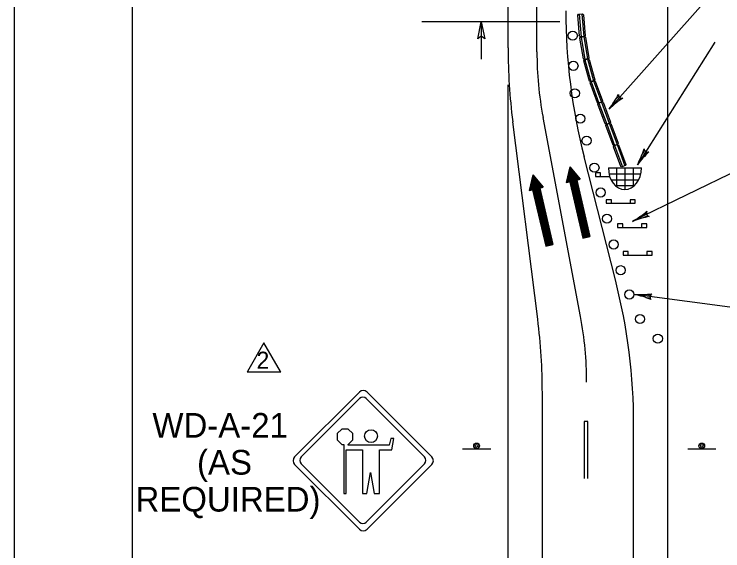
# Model space of a CAD drawing. Extents: x 2171 to 2395, y 134 to 413.
# Drawn here: x 2178.7 to 2238.8, y 274.1 to 319.6 of the extents above; entities that cross this region are included whole.
import ezdxf

# ---------------------------------------------------------------- set-up
doc = ezdxf.new("R2010")
doc.units = 0
for name, color, linetype in [('Level 1', 7, 'Continuous'), ('Level 10', 7, 'Continuous'), ('Level 12', 7, 'Continuous'), ('Level 2', 7, 'Continuous'), ('Level 20', 7, 'Continuous'), ('Level 4', 7, 'Continuous'), ('Level 44', 7, 'Continuous'), ('Level 5', 7, 'Continuous'), ('Level 60', 7, 'Continuous')]:
    doc.layers.add(name, color=color, linetype=linetype)

msp = doc.modelspace()

# ---------------------------------------------------------------- linework, layer by layer
at = {"layer": 'Level 1'}
for p, q in [((2206.522, 284.454), (2206.138, 284.07)), ((2207.064, 284.454), (2206.522, 284.454)), ((2207.448, 284.07), (2207.064, 284.454)), ((2206.138, 284.07), (2206.138, 283.528)), ((2207.448, 283.528), (2207.448, 284.07)), ((2210.68, 283.657), (2210.541, 283.074)), ((2210.924, 283.657), (2210.68, 283.657)), ((2210.765, 282.683), (2210.924, 283.657)), ((2206.138, 283.528), (2206.522, 283.144)), ((2206.522, 283.144), (2206.696, 283.144)), ((2206.696, 283.144), (2206.696, 278.991)), ((2207.064, 283.144), (2207.448, 283.528)), ((2207.064, 283.074), (2207.064, 283.144)), ((2210.541, 283.074), (2207.064, 283.074)), ((2206.886, 278.991), (2206.886, 282.683)), ((2206.886, 282.683), (2208.268, 282.683)), ((2208.268, 282.683), (2208.268, 278.991)), ((2209.718, 278.991), (2209.718, 282.683)), ((2209.718, 282.683), (2210.765, 282.683)), ((2208.635, 278.991), (2208.963, 280.76)), ((2208.963, 280.76), (2209.271, 278.991)), ((2206.696, 278.991), (2206.886, 278.991)), ((2208.268, 278.991), (2208.635, 278.991)), ((2209.271, 278.991), (2209.718, 278.991))]:
    msp.add_line(p, q, dxfattribs=at)
msp.add_circle((2208.998, 283.852), 0.544, dxfattribs=at)
at = {"layer": 'Level 10'}
for p, q in [((2223.061, 316.436), (2223.061, 355.61)), ((2220.618, 316.779), (2220.618, 321.81)), ((2226.76, 293.996), (2223.579, 310.883)), ((2223.127, 293.765), (2221.012, 310.515)), ((2229.715, 297.105), (2227.055, 307.547)), ((2225.864, 306.69), (2225.542, 305.356)), ((2225.824, 306.523), (2227.17, 300.694)), ((2225.864, 306.69), (2227.244, 300.711)), ((2225.864, 306.69), (2226.737, 305.632)), ((2225.973, 306.557), (2227.318, 300.729)), ((2226.082, 306.425), (2227.393, 300.746)), ((2222.723, 306.012), (2222.401, 304.678)), ((2222.683, 305.845), (2224.029, 300.017)), ((2222.723, 306.012), (2224.103, 300.033)), ((2222.723, 306.012), (2223.596, 304.954)), ((2222.832, 305.879), (2224.177, 300.051)), ((2225.662, 305.856), (2225.766, 305.407)), ((2225.703, 306.023), (2226.945, 300.643)), ((2225.743, 306.189), (2227.019, 300.66)), ((2225.782, 306.356), (2227.093, 300.677)), ((2226.191, 306.292), (2227.468, 300.763)), ((2226.3, 306.161), (2227.542, 300.781)), ((2226.41, 306.029), (2226.513, 305.58)), ((2226.519, 305.897), (2226.588, 305.597)), ((2222.521, 305.178), (2222.625, 304.73)), ((2222.562, 305.345), (2223.805, 299.965)), ((2222.602, 305.511), (2223.879, 299.982)), ((2222.641, 305.678), (2223.953, 299.999)), ((2222.941, 305.747), (2224.252, 300.068)), ((2223.05, 305.614), (2224.327, 300.085)), ((2223.159, 305.483), (2224.402, 300.103)), ((2223.269, 305.351), (2223.373, 304.902)), ((2223.378, 305.219), (2223.447, 304.919)), ((2225.542, 305.356), (2225.841, 305.425)), ((2225.582, 305.522), (2225.617, 305.374)), ((2225.622, 305.69), (2225.691, 305.39)), ((2225.841, 305.425), (2226.945, 300.643)), ((2226.438, 305.563), (2226.737, 305.632)), ((2226.438, 305.563), (2227.542, 300.781)), ((2226.628, 305.764), (2226.663, 305.615)), ((2222.401, 304.678), (2222.7, 304.747)), ((2222.441, 304.844), (2222.476, 304.696)), ((2222.481, 305.012), (2222.55, 304.712)), ((2222.7, 304.747), (2223.805, 299.965)), ((2223.298, 304.885), (2223.596, 304.954)), ((2223.298, 304.885), (2224.402, 300.103)), ((2223.487, 305.086), (2223.522, 304.937)), ((2226.945, 300.643), (2227.542, 300.781)), ((2223.805, 299.965), (2224.402, 300.103)), ((2243.047, 294.299), (2231.344, 295.868)), ((2232.292, 295.619), (2232.618, 295.575)), ((2232.344, 295.856), (2232.669, 295.812)), ((2223.521, 177.989), (2223.521, 287.501)), ((2231.261, 177.838), (2231.261, 284.766))]:
    msp.add_line(p, q, dxfattribs=at)
msp.add_lwpolyline([(2218.345, 318.994), (2218.647, 317.542), (2218.346, 317.781), (2218.046, 317.542)], close=True, dxfattribs=at)
for centre, radius, start, end in [((2231.815, 304.15), 8.296, 266.74814, 276.91511), ((2229.485, 287.359), 8.709, 67.99834, 77.67605), ((2232.96, 295.649), 0.303, 118.97466, 225.46268), ((2197.278, 288.443), 30, 0, 10.6664)]:
    msp.add_arc(centre, radius, start, end, dxfattribs=at)
at = {"layer": 'Level 12'}
for centre, radius, start, end in [((2275.509, 319.886), 50, 179.96375, 194.28707), ((2270.618, 316.779), 50, 180, 187.19678), ((2253.061, 316.436), 30, 180, 190.6664), ((2181.261, 284.766), 50, 0, 14.28707), ((2173.521, 287.501), 50, 0, 7.19678)]:
    msp.add_arc(centre, radius, start, end, dxfattribs=at)
at = {"layer": 'Level 2'}
for p, q in [((2225.006, 318.994), (2213.297, 318.994)), ((2218.345, 318.994), (2218.345, 315.821)), ((2227.074, 285.101), (2227.074, 280.263)), ((2227.364, 285.101), (2227.074, 285.101)), ((2227.364, 280.263), (2227.364, 285.101))]:
    msp.add_line(p, q, dxfattribs=at)
at = {"layer": 'Level 20'}
for p, q in [((2234.164, 177.843), (2234.164, 327.612)), ((2220.618, 177.82), (2220.618, 313.635))]:
    msp.add_line(p, q, dxfattribs=at)
at = {"layer": 'Level 4'}
for p, q in [((2226.539, 319.551), (2226.599, 319.622)), ((2226.599, 319.622), (2226.929, 319.649)), ((2226.648, 319.626), (2226.805, 317.715)), ((2226.878, 319.645), (2227.034, 317.733)), ((2227, 319.59), (2226.929, 319.649)), ((2227, 319.59), (2227.145, 317.808)), ((2226.685, 317.77), (2226.539, 319.551)), ((2227.145, 317.808), (2227.086, 317.738)), ((2226.756, 317.71), (2226.685, 317.77)), ((2226.712, 317.607), (2226.766, 317.682)), ((2227.003, 315.844), (2226.712, 317.607)), ((2227.086, 317.738), (2226.756, 317.71)), ((2226.766, 317.682), (2227.093, 317.736)), ((2226.815, 317.69), (2227.128, 315.798)), ((2227.042, 317.727), (2227.354, 315.834)), ((2227.168, 317.682), (2227.093, 317.736)), ((2227.168, 317.682), (2227.459, 315.919)), ((2227.08, 315.789), (2227.003, 315.844)), ((2227.042, 315.679), (2227.089, 315.759)), ((2227.513, 313.955), (2227.042, 315.679)), ((2227.406, 315.843), (2227.08, 315.789)), ((2227.089, 315.759), (2227.409, 315.846)), ((2227.137, 315.773), (2227.641, 313.922)), ((2227.359, 315.833), (2227.862, 313.981)), ((2227.459, 315.919), (2227.406, 315.843)), ((2227.489, 315.8), (2227.409, 315.846)), ((2227.489, 315.8), (2227.959, 314.076)), ((2227.594, 313.909), (2227.513, 313.955)), ((2227.564, 313.797), (2227.604, 313.881)), ((2228.184, 312.121), (2227.564, 313.797)), ((2227.913, 313.995), (2227.594, 313.909)), ((2227.604, 313.881), (2227.914, 313.995)), ((2227.65, 313.898), (2228.315, 312.099)), ((2227.866, 313.978), (2228.53, 312.178)), ((2227.959, 314.076), (2227.913, 313.995)), ((2227.999, 313.957), (2227.914, 313.995)), ((2227.999, 313.957), (2228.618, 312.281)), ((2228.27, 312.082), (2228.184, 312.121)), ((2228.232, 311.998), (2228.271, 312.082)), ((2228.852, 310.322), (2228.232, 311.998)), ((2228.579, 312.196), (2228.27, 312.082)), ((2228.271, 312.082), (2228.582, 312.196)), ((2228.318, 312.099), (2228.982, 310.3)), ((2228.533, 312.179), (2229.198, 310.379)), ((2228.618, 312.281), (2228.579, 312.196)), ((2228.666, 312.158), (2228.582, 312.196)), ((2228.666, 312.158), (2229.285, 310.482)), ((2228.937, 310.283), (2228.852, 310.322)), ((2228.892, 310.197), (2228.932, 310.281)), ((2229.512, 308.521), (2228.892, 310.197)), ((2228.932, 310.281), (2229.242, 310.396)), ((2229.247, 310.397), (2228.937, 310.283)), ((2228.978, 310.299), (2229.643, 308.5)), ((2229.194, 310.378), (2229.858, 308.578)), ((2229.327, 310.357), (2229.242, 310.396)), ((2229.285, 310.482), (2229.247, 310.397)), ((2229.327, 310.357), (2229.946, 308.681)), ((2229.598, 308.482), (2229.512, 308.521)), ((2229.555, 308.396), (2229.595, 308.48)), ((2230.176, 306.72), (2229.555, 308.396)), ((2229.595, 308.48), (2229.906, 308.595)), ((2229.907, 308.597), (2229.598, 308.482)), ((2229.641, 308.498), (2230.306, 306.699)), ((2229.857, 308.577), (2230.522, 306.777)), ((2229.99, 308.556), (2229.906, 308.595)), ((2229.946, 308.681), (2229.907, 308.597)), ((2229.99, 308.556), (2230.609, 306.88)), ((2229.116, 306.598), (2231.922, 306.598)), ((2229.819, 306.598), (2229.819, 305.002)), ((2230.261, 306.681), (2230.176, 306.72)), ((2230.571, 306.796), (2230.261, 306.681)), ((2230.519, 306.598), (2230.519, 304.756)), ((2230.609, 306.88), (2230.571, 306.796)), ((2231.219, 306.598), (2231.219, 305.002)), ((2229.169, 306.098), (2231.868, 306.098)), ((2229.342, 305.598), (2231.696, 305.598)), ((2229.706, 305.098), (2231.332, 305.098))]:
    msp.add_line(p, q, dxfattribs=at)
msp.add_ellipse((2230.519, 306.605), major_axis=(0, -1.85), ratio=0.758621, start_param=4.716532, end_param=7.849839, dxfattribs=at)
at = {"layer": 'Level 44'}
for p, q in [((2208.014, 287.583), (2202.52, 282.097)), ((2214.148, 282.097), (2208.663, 287.583)), ((2203.07, 282.093), (2208.014, 287.03)), ((2208.598, 287.03), (2213.536, 282.093)), ((2219.151, 282.755), (2216.755, 282.755)), ((2238.239, 282.755), (2235.843, 282.755)), ((2202.52, 281.446), (2208.014, 275.955)), ((2202.525, 281.446), (2202.52, 281.446)), ((2208.014, 276.566), (2203.07, 281.506)), ((2213.536, 281.506), (2208.598, 276.566)), ((2208.663, 275.955), (2214.148, 281.446))]:
    msp.add_line(p, q, dxfattribs=at)
for centre, radius in [((2217.947, 283.023), 0.24), ((2217.947, 283.023), 0.12), ((2237.036, 283.023), 0.24), ((2237.036, 283.023), 0.12)]:
    msp.add_circle(centre, radius, dxfattribs=at)
for centre, radius, start, end in [((2208.337, 287.259), 0.459, 45, 135), ((2208.305, 286.738), 0.413, 45, 135), ((2202.849, 281.771), 0.459, 135, 224.99999), ((2203.365, 281.799), 0.413, 135, 224.99999), ((2213.244, 281.799), 0.413, 315, 45), ((2213.826, 281.771), 0.459, 315, 45), ((2208.305, 276.859), 0.413, 225, 315), ((2208.337, 276.283), 0.459, 225, 315)]:
    msp.add_arc(centre, radius, start, end, dxfattribs=at)
at = {"layer": 'Level 5'}
for p, q in [((2238.207, 321.737), (2229.185, 311.591)), ((2238.146, 317.26), (2231.577, 306.871)), ((2229.761, 312.414), (2229.981, 312.658)), ((2229.927, 312.238), (2230.148, 312.481)), ((2232.005, 307.773), (2232.18, 308.051)), ((2232.199, 307.628), (2232.374, 307.905)), ((2241.683, 307.198), (2231.177, 302.067)), ((2228.46, 306.171), (2228.024, 306.171)), ((2228.024, 306.171), (2228.024, 305.865)), ((2228.024, 305.865), (2229.233, 305.865)), ((2228.459, 305.866), (2228.46, 306.171)), ((2229.377, 303.901), (2228.941, 303.901)), ((2228.941, 303.901), (2228.941, 303.595)), ((2228.941, 303.595), (2231.402, 303.595)), ((2229.376, 303.596), (2229.377, 303.901)), ((2231.402, 303.901), (2230.967, 303.902)), ((2230.967, 303.901), (2230.967, 303.595)), ((2231.402, 303.595), (2231.402, 303.901)), ((2232.015, 302.61), (2232.31, 302.755)), ((2232.104, 302.385), (2232.399, 302.529)), ((2230.34, 301.861), (2229.904, 301.861)), ((2229.904, 301.861), (2229.904, 301.555)), ((2230.339, 301.555), (2230.34, 301.861)), ((2232.366, 301.861), (2231.931, 301.862)), ((2231.931, 301.861), (2231.931, 301.555)), ((2232.366, 301.555), (2232.366, 301.861)), ((2229.904, 301.555), (2232.366, 301.555)), ((2230.798, 299.503), (2230.363, 299.503)), ((2230.363, 299.503), (2230.363, 299.196)), ((2230.363, 299.196), (2232.825, 299.197)), ((2230.798, 299.197), (2230.798, 299.503)), ((2232.825, 299.503), (2232.389, 299.503)), ((2232.389, 299.503), (2232.389, 299.197)), ((2232.825, 299.197), (2232.825, 299.503))]:
    msp.add_line(p, q, dxfattribs=at)
for centre in [(2226.101, 317.817), (2226.158, 315.256), (2226.274, 312.925), (2226.748, 310.778), (2227.269, 308.914), (2227.937, 306.61), (2228.47, 304.514), (2228.996, 302.288), (2229.571, 300.105), (2230.161, 297.921), (2230.901, 295.866), (2231.795, 293.781), (2233.315, 292.119)]:
    msp.add_circle(centre, 0.388, dxfattribs=at)
for centre, radius, start, end in [((2222.634, 316.689), 8.296, 322.14539, 332.31237), ((2235.132, 305.237), 8.709, 123.3956, 133.07331), ((2230.281, 312.805), 0.303, 174.37192, 280.85994), ((2224.247, 310.753), 8.296, 332.0857, 342.25268), ((2232.45, 308.247), 0.303, 184.31222, 290.80024), ((2238.534, 301.63), 8.709, 133.3359, 143.01361), ((2226.977, 309.22), 8.296, 300.4195, 310.58648), ((2232.643, 302.78), 0.303, 152.64603, 259.13405), ((2234.348, 293.954), 8.709, 101.66971, 111.34742)]:
    msp.add_arc(centre, radius, start, end, dxfattribs=at)
at = {"layer": 'Level 60'}
for points in [[(2394.748, 412.757), (2178.748, 412.757), (2178.748, 133.757), (2394.748, 133.757)], [(2375.622, 401.948), (2188.748, 401.948), (2188.748, 144.566), (2375.622, 144.566)]]:
    msp.add_lwpolyline(points, close=True, dxfattribs=at)
for points in [[(2199.925, 291.765), (2198.532, 289.34)], [(2201.319, 289.34), (2199.925, 291.765)], [(2198.532, 289.34), (2198.506, 289.295), (2201.345, 289.295), (2201.319, 289.34)]]:
    msp.add_lwpolyline(points, dxfattribs=at)

# ---------------------------------------------------------------- texts
at = {"layer": 'Level 10'}
for s, p in [('WD-A-21', (2190.464, 283.725)), ('(AS ', (2194.249, 280.591)), ('REQUIRED)', (2189.032, 277.457))]:
    msp.add_text(s, height=2.09, dxfattribs=at).set_placement(p)
at = {"layer": 'Level 60'}
msp.add_text('2', height=1.448, rotation=360, dxfattribs=at).set_placement((2199.298, 289.564))

doc.saveas('drawing.dxf')
